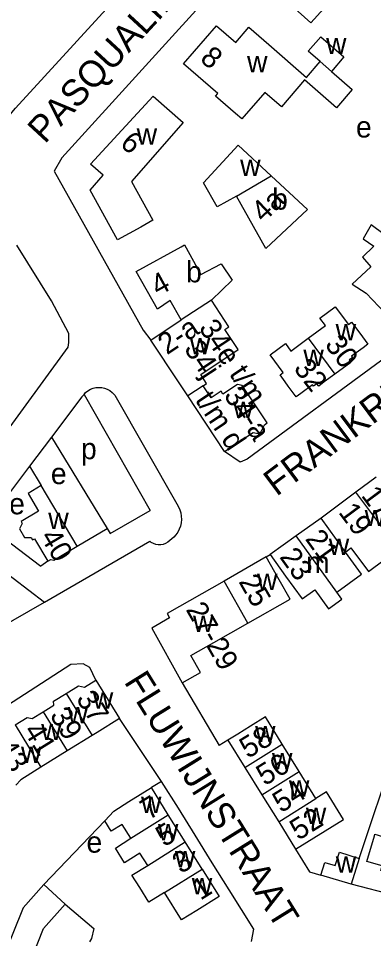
# Model space of a CAD drawing. Extents: x 159294 to 161936, y 384538 to 386517.
# Drawn here: x 160524.5 to 160591.7, y 385144.8 to 385318.7 of the extents above; entities that cross this region are included whole.
import ezdxf

# ---------------------------------------------------------------- set-up
doc = ezdxf.new("R2010")
doc.units = 0
for name, color, linetype in [('BLT_Basislijn', 7, 'Continuous'), ('BLT_Bebouwing', 7, 'Continuous'), ('BLT_Centroide', 7, 'Continuous'), ('BLT_Huisnummer', 7, 'Continuous'), ('BLT_Huisnummer_ tussenligend', 7, 'Continuous'), ('BLT_Huisnummer_reeks', 7, 'Continuous'), ('BLT_Onderverdeling_panden', 7, 'Continuous'), ('BLT_Straatnaam', 7, 'Continuous')]:
    doc.layers.add(name, color=color, linetype=linetype)

msp = doc.modelspace()

# ---------------------------------------------------------------- linework, layer by layer
at = {"layer": 'BLT_Basislijn'}
for p, q in [((160536.52, 385247.15), (160530.79, 385239.58)), ((160536.52, 385247.15), (160536.92, 385247.64)), ((160536.92, 385247.64), (160549.41, 385225.72)), ((160542.77, 385247.47), (160554.46, 385226.96)), ((160530.79, 385239.58), (160526.64, 385234.1)), ((160530.79, 385239.58), (160541.31, 385222.28)), ((160526.64, 385234.1), (160518.31, 385223.11)), ((160526.64, 385234.1), (160528.84, 385230.41)), ((160541.87, 385221.36), (160549.41, 385225.72)), ((160518.31, 385223.11), (160528.74, 385215.21)), ((160535.63, 385218.95), (160541.31, 385222.28)), ((160541.31, 385222.28), (160541.87, 385221.36)), ((160553.9, 385220.66), (160552.76, 385219.7)), ((160515.29, 385219.12), (160529.44, 385208.41)), ((160529.44, 385208.41), (160549.34, 385219.91)), ((160571.38, 385216.92), (160572.15, 385217.38)), ((160530.07, 385216.12), (160528.74, 385215.21)), ((160511.06, 385197.79), (160529.44, 385208.41)), ((160555.5, 385193.12), (160562.5, 385181.32)), ((160564.15, 385182.31), (160562.5, 385181.32)), ((160588.95, 385159.94), (160596.34, 385182.09)), ((160551.57, 385174.5), (160549.66, 385173.34)), ((160621.33, 385146.29), (160587.42, 385155.1))]:
    msp.add_line(p, q, dxfattribs=at)
for points in [[(160518.57, 385288.1), (160518.69, 385292.74), (160519.86, 385296.14), (160521.32, 385298.56), (160523.97, 385301.7), (160563.77, 385345.18), (160565.49, 385348.1)], [(160578.3, 385342.47), (160532.7, 385292.36), (160531.3, 385289.81), (160548.08, 385259.76), (160549.53, 385257.91)], [(160623.78, 385281.57), (160615.83, 385273.75), (160610.43, 385268.51), (160604.75, 385263.54), (160594.19, 385254.81), (160567.79, 385235.43), (160566.45, 385234.84), (160563.51, 385236.84)], [(160519.93, 385236.91), (160520.71, 385238.51), (160533.91, 385256.55), (160534.04, 385257.47), (160534.04, 385259.15), (160530.76, 385265.31), (160524.24, 385275.83)], [(160536.92, 385247.64), (160537.22, 385247.99), (160537.65, 385248.33), (160538.13, 385248.6), (160538.65, 385248.8), (160539.18, 385248.93), (160539.73, 385248.97), (160540.28, 385248.93), (160540.81, 385248.82), (160541.33, 385248.63), (160541.81, 385248.36), (160542.25, 385248.03), (160542.63, 385247.64), (160542.77, 385247.47)], [(160554.46, 385226.96), (160554.79, 385226.42), (160555.04, 385225.84), (160555.22, 385225.24), (160555.32, 385224.62), (160555.34, 385223.99), (160555.28, 385223.37), (160555.15, 385222.76), (160554.93, 385222.17), (160554.64, 385221.61), (160554.29, 385221.09), (160553.9, 385220.66)], [(160552.76, 385219.7), (160552.35, 385219.47), (160551.9, 385219.3), (160551.44, 385219.22), (160550.97, 385219.21), (160550.51, 385219.29), (160550.06, 385219.44), (160549.65, 385219.67), (160549.34, 385219.91)], [(160539.18, 385193.65), (160537.99, 385196.02), (160536.77, 385196.74), (160534.45, 385196.63), (160518.96, 385186.67), (160513.84, 385182.44), (160508.95, 385176.97), (160504.28, 385169.95), (160500, 385161.23), (160490.84, 385138.4)], [(160551.57, 385174.5), (160551.46, 385174.67), (160543.66, 385186.39)], [(160568.61, 385144.29), (160569.05, 385146.6), (160564.4, 385154.03), (160561.13, 385159.15), (160557.92, 385164.38), (160554.81, 385169.45), (160551.57, 385174.5)], [(160529.31, 385155.02), (160540.85, 385167.04)], [(160576.93, 385161.69), (160579.56, 385157.4), (160581.74, 385156.77)], [(160533.36, 385151.29), (160538.79, 385146.74), (160538.34, 385144.86), (160537.96, 385144.22)]]:
    msp.add_lwpolyline(points, dxfattribs=at)
at = {"layer": 'BLT_Bebouwing'}
for p, q in [((160549.53, 385257.91), (160555.29, 385261.73)), ((160563.51, 385236.84), (160556.53, 385247.37)), ((160592.19, 385232.03), (160588.36, 385229.17)), ((160535.63, 385218.95), (160528.84, 385230.41)), ((160588.36, 385229.17), (160581.77, 385224.28)), ((160581.77, 385224.28), (160577.04, 385220.89)), ((160577.04, 385220.89), (160572.15, 385217.38)), ((160571.38, 385216.92), (160563.4, 385212.38)), ((160563.4, 385212.38), (160552.63, 385206.26)), ((160552.63, 385206.26), (160553.12, 385205.39)), ((160539.18, 385193.65), (160543.66, 385186.39)), ((160538.44, 385183.16), (160533.75, 385180.27)), ((160566, 385183.46), (160564.15, 385182.31)), ((160564.15, 385182.31), (160567.35, 385177.16)), ((160533.75, 385180.27), (160528.76, 385177.19)), ((160577.61, 385176.39), (160574.42, 385181.54)), ((160567.35, 385177.16), (160570.54, 385172)), ((160580.77, 385171.29), (160577.61, 385176.39)), ((160552.86, 385168.21), (160549.66, 385173.34)), ((160570.54, 385172), (160573.74, 385166.85)), ((160556.06, 385163.07), (160552.86, 385168.21)), ((160573.74, 385166.85), (160576.93, 385161.69)), ((160559.27, 385157.93), (160556.06, 385163.07)), ((160588.95, 385159.94), (160587.42, 385155.1)), ((160587.42, 385155.1), (160581.74, 385156.77)), ((160533.36, 385151.29), (160529.31, 385155.02))]:
    msp.add_line(p, q, dxfattribs=at)
for points in [[(160588.42, 385327.33), (160579.84, 385317.85), (160574.4, 385322.77), (160570.69, 385326.13), (160579.3, 385335.65), (160588.42, 385327.33)], [(160583.7, 385308.68), (160587.67, 385305.23), (160584.69, 385301.81), (160578.62, 385307.08), (160574.27, 385301.96), (160571.1, 385304.71), (160566.74, 385299.69), (160565.57, 385300.72), (160561.79, 385303.99), (160562.21, 385304.48), (160555.72, 385310.12), (160561.97, 385317.31), (160565.62, 385314.15), (160568.12, 385317.03), (160571.9, 385313.75)], [(160581.58, 385310.52), (160579.32, 385312.49), (160581.7, 385315.23), (160586.09, 385311.42), (160583.7, 385308.68)], [(160571.9, 385313.75), (160579.03, 385307.55), (160581.58, 385310.52)], [(160549.98, 385304.02), (160555.68, 385298.99), (160545.88, 385287.89), (160549.93, 385280.54), (160547.64, 385279.27), (160543.26, 385276.86), (160538.06, 385286.26), (160540.54, 385289.05), (160538.17, 385291.16), (160549.98, 385304.02)], [(160565.77, 385285.11), (160562.12, 385283.08), (160559.52, 385287.62), (160566.09, 385294.73), (160572.32, 385288.97)], [(160572.32, 385288.97), (160579.22, 385282.6), (160571.34, 385275.21), (160565.77, 385285.11)], [(160598.36, 385274.39), (160591.25, 385279.71), (160589.7, 385277.04), (160591.76, 385275.62), (160589.61, 385273.6), (160591.19, 385271.76), (160587.67, 385268.44), (160590.29, 385266.78), (160592.67, 385264.25), (160596.49, 385260.19), (160604.57, 385267.8)], [(160555.29, 385261.73), (160553.21, 385265.37), (160550.81, 385263.77), (160546.77, 385270.85), (160555.29, 385275.55), (160555.93, 385275.9), (160559.03, 385270.29), (160562.89, 385272.32), (160564.94, 385269.23), (160561.01, 385265.45)], [(160559.45, 385249.27), (160560.1, 385249.7), (160558.99, 385251.39), (160566.1, 385256.1), (160563.56, 385259.92), (160564.34, 385260.43), (160561.01, 385265.45)], [(160579.33, 385258.25), (160582.59, 385260.66), (160581.55, 385262.07), (160584.45, 385264.21), (160586.93, 385260.84), (160587.53, 385261.29), (160589.09, 385259.18), (160590.6, 385257.13), (160589.71, 385256.47), (160587.49, 385254.86), (160587.69, 385254.58), (160587.09, 385254.16), (160587.39, 385253.68), (160584.34, 385251.44)], [(160556.53, 385247.37), (160554.78, 385250), (160549.53, 385257.91)], [(160584.34, 385251.44), (160582.37, 385250), (160581.31, 385249.22), (160580.95, 385249.61), (160580.35, 385249.19), (160580.15, 385249.45), (160577.93, 385247.83), (160577.06, 385247.19), (160575.55, 385249.21), (160574.97, 385250), (160573.99, 385251.31), (160574.6, 385251.76), (160572.12, 385255.12), (160575.02, 385257.26), (160576.06, 385255.84), (160579.33, 385258.25)], [(160563.51, 385236.84), (160568.93, 385240.44), (160569.87, 385240.25), (160570.41, 385240.61), (160571.05, 385241.89), (160571.57, 385242.24), (160568.8, 385246.4), (160566.86, 385249.33), (160565.97, 385249.51), (160563.2, 385247.67), (160562.84, 385248.22), (160560.97, 385246.99), (160559.45, 385249.27)], [(160528.84, 385230.41), (160526.33, 385228.91), (160528.3, 385225.59), (160525.01, 385223.63), (160525.25, 385223.23), (160524.69, 385222.23)], [(160524.69, 385222.23), (160525.68, 385220.57), (160526.91, 385220.59), (160527.17, 385220.16), (160527.54, 385220.37), (160530.07, 385216.12)], [(160586.37, 385217.86), (160587.39, 385218.62), (160590.7, 385214.18), (160596.38, 385218.41), (160593.06, 385222.85)], [(160530.07, 385216.12), (160530.63, 385216.46), (160531.21, 385216.31), (160535.63, 385218.95)], [(160567.92, 385204.44), (160575.9, 385208.97), (160573.85, 385212.58), (160571.38, 385216.92)], [(160572.15, 385217.38), (160575.06, 385213.32), (160578.18, 385208.98), (160580.59, 385210.72), (160583.16, 385207.14), (160585.7, 385208.95), (160584.74, 385210.29)], [(160584.74, 385210.29), (160589.39, 385213.65), (160586.37, 385217.86)], [(160553.12, 385205.39), (160549.73, 385203.46), (160555.5, 385193.12)], [(160555.5, 385193.12), (160558.97, 385195.09), (160557.15, 385198.31), (160561.49, 385200.78), (160567.92, 385204.44)], [(160533.52, 385191.12), (160535.9, 385192.59), (160537.03, 385192.32), (160539.18, 385193.65)], [(160529.19, 385187.65), (160531.24, 385188.92), (160531.14, 385189.65), (160533.52, 385191.12)], [(160523.89, 385185.18), (160526.19, 385186.6), (160527.13, 385186.38), (160529.19, 385187.65)], [(160543.66, 385186.39), (160539.41, 385183.76), (160538.44, 385183.16)], [(160574.42, 385181.54), (160571.22, 385186.7), (160568.4, 385184.95), (160566, 385183.46)], [(160528.76, 385177.19), (160524.97, 385174.84), (160524.04, 385173.83)], [(160540.85, 385167.04), (160542.55, 385168.91), (160545.41, 385170.7), (160549.66, 385173.34)], [(160576.93, 385161.69), (160586.02, 385167.32), (160582.78, 385172.54), (160580.77, 385171.29)], [(160545.75, 385163.78), (160544.12, 385166.4), (160542.05, 385165.12), (160540.85, 385167.04)], [(160598.86, 385155.95), (160593.03, 385157.67), (160593.29, 385158.56), (160590.43, 385159.4), (160591.84, 385164.2), (160591.94, 385164.53), (160594.84, 385163.67), (160595.42, 385165.64), (160601.21, 385163.93)], [(160548.96, 385158.64), (160547.5, 385160.97), (160544.56, 385159.14), (160542.85, 385161.88), (160545.75, 385163.78)], [(160581.74, 385156.77), (160582.46, 385159.21), (160584.44, 385158.63), (160585.23, 385161.12), (160588.95, 385159.94)], [(160552.16, 385153.5), (160549.15, 385151.71), (160547.45, 385154.44), (160545.99, 385156.78), (160548.96, 385158.64)], [(160559.27, 385157.93), (160562.47, 385152.79), (160558.23, 385150.15), (160555.36, 385148.36), (160552.16, 385153.5)], [(160529.31, 385155.02), (160525.41, 385150.6), (160516.08, 385127.65)], [(160516.89, 385101.51), (160526.03, 385123.99), (160521.03, 385126.02), (160529.26, 385146.71), (160533.36, 385151.29)]]:
    msp.add_lwpolyline(points, dxfattribs=at)
at = {"layer": 'BLT_Onderverdeling_panden'}
for p, q in [((160581.58, 385310.52), (160583.7, 385308.68)), ((160565.77, 385285.11), (160572.32, 385288.97)), ((160561.01, 385265.45), (160555.29, 385261.73)), ((160579.33, 385258.25), (160584.34, 385251.44)), ((160559.45, 385249.27), (160556.53, 385247.37)), ((160593.06, 385222.85), (160588.36, 385229.17)), ((160584.74, 385210.29), (160577.04, 385220.89)), ((160567.92, 385204.44), (160563.4, 385212.38)), ((160533.52, 385191.12), (160538.44, 385183.16)), ((160529.19, 385187.65), (160533.75, 385180.27)), ((160523.89, 385185.18), (160528.76, 385177.19)), ((160567.35, 385177.16), (160574.42, 385181.54)), ((160570.54, 385172), (160577.61, 385176.39)), ((160573.74, 385166.85), (160580.77, 385171.29)), ((160545.75, 385163.78), (160552.86, 385168.21)), ((160548.96, 385158.64), (160556.06, 385163.07)), ((160552.16, 385153.5), (160559.27, 385157.93))]:
    msp.add_line(p, q, dxfattribs=at)
msp.add_lwpolyline([(160586.37, 385217.86), (160584.68, 385220.21), (160581.77, 385224.28)], dxfattribs=at)

# ---------------------------------------------------------------- texts
at = {"layer": 'BLT_Centroide'}
for s, p in [('w', (160582.7, 385311.94)), ('w', (160567.76, 385308.5)), ('e', (160588.36, 385296.18)), ('w', (160546.88, 385294.83)), ('w', (160566.45, 385288.91)), ('b', (160572.5, 385282.55)), ('b', (160556.23, 385268.81)), ('w', (160584.52, 385257.84)), ('w', (160556.94, 385255.22)), ('w', (160578.41, 385253.03)), ('w', (160565.12, 385243.19)), ('p', (160536.35, 385235.39)), ('e', (160530.65, 385230.69)), ('e', (160522.76, 385224.98)), ('w', (160590, 385222.75)), ('w', (160530.16, 385222.19)), ('w', (160583.22, 385217.31)), ('m', (160578.92, 385213.92)), ('w', (160569.65, 385210.69)), ('w', (160557.54, 385202.75)), ('w', (160538.59, 385188.27)), ('w', (160533.81, 385185.48)), ('w', (160528.81, 385182.31)), ('w', (160569.28, 385181.94)), ('w', (160525, 385178.02)), ('w', (160572.48, 385176.78)), ('w', (160575.68, 385171.62)), ('w', (160547.7, 385168.56)), ('w', (160578.88, 385166.47)), ('w', (160550.91, 385163.41)), ('e', (160537.39, 385161.05)), ('w', (160554.11, 385158.28)), ('w', (160584.55, 385157.27)), ('w', (160557.31, 385153.16))]:
    msp.add_text(s, height=4, dxfattribs=at).set_placement(p)
at = {"layer": 'BLT_Huisnummer'}
for s, rotation, p in [('8', 319.0071, (160558.67, 385310.8)), ('4a', 43.1807, (160570.86, 385279.97)), ('4', 28.8637, (160550.94, 385266.12)), ('30', 306.3912, (160582.33, 385257.02)), ('32', 307.6077, (160576.43, 385252.51)), ('19', 306.7019, (160584.92, 385225.35)), ('21', 305.6678, (160578.63, 385220.33)), ('40', 300.662, (160528.54, 385220.76)), ('23', 305.6675, (160573.78, 385216.91)), ('25', 299.6189, (160566.08, 385212.27)), ('37', 301.7066, (160535.32, 385190.16)), ('41', 301.7066, (160525.37, 385184.08)), ('58', 31.7966, (160567.93, 385178.73)), ('7', 31.9437, (160549.16, 385167.11)), ('52', 31.7929, (160577.45, 385163.27)), ('1', 31.9424, (160558.94, 385151.95))]:
    msp.add_text(s, height=4, rotation=rotation, dxfattribs=at).set_placement(p)
at = {"layer": 'BLT_Huisnummer_ tussenligend'}
for s, rotation, p in [('17', 306.6903, (160589.22, 385228.52)), ('39', 301.7066, (160530.34, 385187.01)), ('43', 301.7066, (160520.15, 385180.97)), ('56', 31.7929, (160571.1, 385173.57)), ('54', 31.7929, (160574.18, 385168.46)), ('5', 31.9424, (160552.09, 385162.03)), ('3', 31.9424, (160555.24, 385156.96))]:
    msp.add_text(s, height=4, rotation=rotation, dxfattribs=at).set_placement(p)
at = {"layer": 'BLT_Huisnummer_reeks'}
for s, rotation, p in [('6', 318.3065, (160543.53, 385294.77)), ('2-a', 33.5749, (160552.61, 385255.02)), ('34e t/m', 303.5763, (160558.51, 385260.19)), ('34j', 303.5763, (160555.72, 385256.26)), ('t/m d', 303.5763, (160557.81, 385246.59)), ('34-a', 303.5763, (160563.24, 385247.45)), ('27-29', 299.636, (160556.09, 385207.01))]:
    msp.add_text(s, height=4, rotation=rotation, dxfattribs=at).set_placement(p)
at = {"layer": 'BLT_Straatnaam'}
for s, rotation, p in [('PASQUALINISTRAAT', 47.2565, (160529.49, 385294.84)), ('FRANKRIJKSTRAAT', 36.7948, (160573.32, 385228.26)), ('FLUWIJNSTRAAT', 301.8082, (160544.39, 385193.34))]:
    msp.add_text(s, height=5, rotation=rotation, dxfattribs=at).set_placement(p)

doc.saveas('drawing.dxf')
